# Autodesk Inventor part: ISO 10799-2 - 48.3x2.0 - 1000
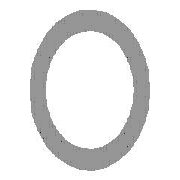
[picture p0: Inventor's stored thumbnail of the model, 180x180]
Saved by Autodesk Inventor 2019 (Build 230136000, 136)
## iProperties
IsCustomPart: 1
Created: 2018-01
Part Number: ISO 10799-2 - 48.3x2.0 - 1000
Material: Acier, doux
Description: Aciers de construction - Coupes creuses profilées formées à froid, soudées
Document SubType Name: Modeling
Standard: ISO
Designer: Fabian Perrée
Standard Revision: First edition 2011-09-15
Standards Organization: ISO
Language: fr-FR
Size Designation: 48.3x2.0
Categories: <MemberInstance><Categories><Category DisplayName="Profilés" InternalName="089c4875-fa83-4c05-b084-43b9cc11f5ed" Mnemonic="GRDR"><CategoryParameter DisplayName=
Stock Number: 48.3x2.0
Density: 7.85 g/cm^3
Appearance: Semi-poli
Mass: 2283.66 g
Surface Area: 2914.93 cm^2
Volume: 290.911 cm^3
_CCFamilyMember: 14
_CCFamilyDisplayName: ISO 10799-2 (Profils creux circulaires - Formés à froid) - Aciers de construction - Coupes creuses profilées formées à froid, soudées
_FrameMemberDoc: Frame Member File
_Version: 15.0.0
_GetPNFromCC: 1
G_L: 1000,000 mm
G_W: 48,300 mm
G_H: 48,300 mm
Author: Fabian Perrée
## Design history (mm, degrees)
node "Plan de départ"
node "Plan de fin"
sketch "Esquisse"
  geometry: C1 r 22.15 at (0, 0); C2 r 24.15 at (0, 0); 2 further points
  constraints: 3 coincident, 2 centre point
  dimensions: "d0" = 48.3 diameter of C2 (= G_H); "d1" = 2 radial gap between concentric circles of C2 C1 (= G_T)
extrude "Corps" new body sketch "Esquisse" stored distance "d2" = 1000 (= G_L); taper "d3" = 0 deg
node "Driven Length"
  sketch "Sketch3"
    geometry: L1 (0, 0)-(10, 0) reference
    constraints: 2 end point, 1 horizontal
  workplane "Work Plane3"
  sketch "Sketch4"
    geometry: L1 (-2, 0)-(12, 0) reference; L2 (-2, 1000)-(12, 1000) reference
    dimensions: "d7" = 1000 distance between parallel lines of L1 L2 (derived)
body "Solid1"
other parameters: "G_H" = 48.3 [user parameter; used in 1 equation term], "G_T" = 2 [user parameter; used in 1 equation term], "G_L" = 1000 (= d7) [user parameter; used in 1 equation term], "G_OFFSET_START" = 0 [user parameter; used in 1 equation term], "G_OFFSET_END" = 0 [user parameter; used in 1 equation term], "d4" = 0 (computed from G_OFFSET_START), "d6" = 90 deg, "MAS" = 0.228 [user parameter]
